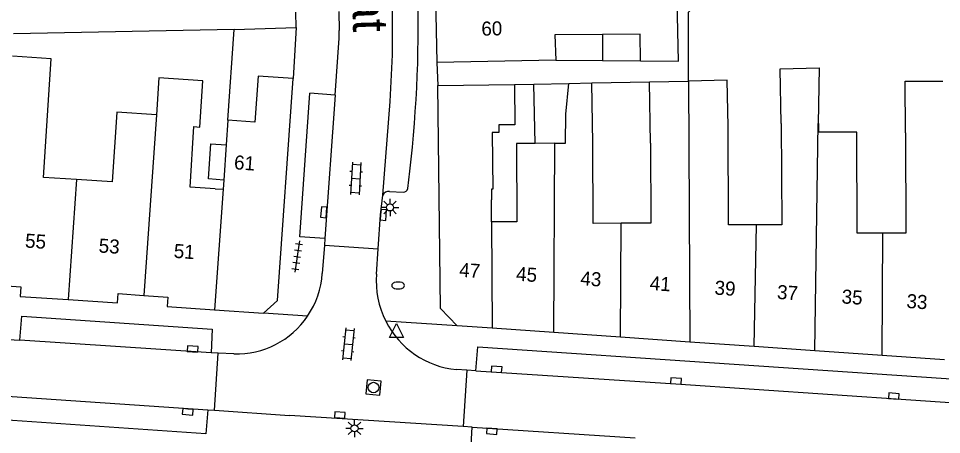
# Model space of a CAD drawing. Extents: x 132998 to 136004, y 396998 to 398512.
# Drawn here: x 133158 to 133223.8, y 397332.1 to 397361.7 of the extents above; entities that cross this region are included whole.
import ezdxf

# ---------------------------------------------------------------- set-up
doc = ezdxf.new("R2010")
doc.units = 0
for name, color, linetype in [('gg-afsc-erfafscheiding', 7, 'Continuous'), ('gg-afsc-muur', 7, 'Continuous'), ('gg-anno-huisnummerreeks BGT', 7, 'Continuous'), ('gg-anno-openbare ruimte label', 7, 'Continuous'), ('gg-bbg-gedigitaliseerde bebouwing', 7, 'Continuous'), ('gg-bbg-gedigitaliseerde bijgebouw', 7, 'Continuous'), ('gg-bbg-hoofdgebouw', 7, 'Continuous'), ('gg-bbg-luifel en loopbrug', 7, 'Continuous'), ('gg-bbg-tussenscheiding', 7, 'Continuous'), ('gg-knt-verharding', 7, 'Continuous'), ('gg-knt-verharding nz', 7, 'Continuous'), ('gt-grn-weggrens', 7, 'Continuous'), ('gt-symb-brandkraan', 7, 'Continuous'), ('gt-symb-klinker verharding', 7, 'Continuous'), ('gt-symb-kolk', 7, 'Continuous'), ('gt-symb-lichtmast', 7, 'Continuous'), ('gt-symb-rioolschacht', 7, 'Continuous'), ('gt-symb-tegel verharding', 7, 'Continuous'), ('gt-symb-waterafsluiter', 7, 'Continuous')]:
    doc.layers.add(name, color=color, linetype=linetype)

# ---------------------------------------------------------------- blocks, each defined once
blk = doc.blocks.new('gt0-KOLK')
at = {"layer": 'gt-symb-kolk'}
blk.add_lwpolyline([(0, 0), (0.375, 0), (0.375, 0.4), (-0.375, 0.4), (-0.375, 0), (0, 0)], dxfattribs=at)
blk = doc.blocks.new('gt0-KL1')
at = {"layer": 'gt-symb-klinker verharding'}
for p, q in [((-1.15, 0.3), (1.15, 0.3)), ((-1, -0.3), (-1, 0.3)), ((-0.5, 0.3), (-0.5, 0.45)), ((0, -0.3), (0, 0.3)), ((0.5, 0.3), (0.5, 0.45)), ((1, -0.3), (1, 0.3)), ((-1.15, -0.3), (1.15, -0.3)), ((-0.5, -0.45), (-0.5, -0.3)), ((0.5, -0.45), (0.5, -0.3))]:
    blk.add_line(p, q, dxfattribs=at)
blk = doc.blocks.new('gt0-LMAST')
at = {"layer": 'gt-symb-lichtmast'}
for p, q in [((-0.182, 0.173), (-0.447, 0.438)), ((-0.005, 0.246), (-0.005, 0.621)), ((0.172, 0.173), (0.437, 0.438)), ((-0.255, -0.004), (-0.63, -0.004)), ((-0.182, -0.181), (-0.447, -0.446)), ((-0.005, -0.254), (-0.005, -0.629)), ((0.437, -0.446), (0.172, -0.181)), ((0.245, -0.004), (0.62, -0.004))]:
    blk.add_line(p, q, dxfattribs=at)
blk.add_circle((-0.005, -0.004), 0.25, dxfattribs=at)
blk = doc.blocks.new('gt0-WAFSL')
at = {"layer": 'gt-symb-waterafsluiter'}
for p, q in [((-0.5, -0.333), (0, 0.667)), ((0, 0.667), (0.5, -0.333)), ((0.5, -0.333), (-0.5, -0.333))]:
    blk.add_line(p, q, dxfattribs=at)
blk = doc.blocks.new('gt0-BR')
at = {"layer": 'gt-symb-brandkraan'}
for centre, radius, start, end in [((-0.244, 0), 0.206, 107.56694, 252.43307), ((0.599, -2.664), 3, 106.89205, 107.56694), ((0, -0.691), 0.938, 73.10799, 106.89205), ((-0.599, -2.664), 3, 72.43309, 73.10799), ((0.244, 0), 0.206, 287.56695, 72.43309), ((0.599, 2.664), 3, 252.43307, 253.10797), ((0, 0.691), 0.938, 253.10797, 286.89206), ((-0.599, 2.664), 3, 286.89206, 287.56695)]:
    blk.add_arc(centre, radius, start, end, dxfattribs=at)
blk = doc.blocks.new('gt0-TEG1')
at = {"layer": 'gt-symb-tegel verharding'}
for p, q in [((-1.125, 0), (1.125, 0)), ((-0.9, -0.25), (-0.9, 0.25)), ((-0.45, -0.25), (-0.45, 0.25)), ((0, -0.25), (0, 0.25)), ((0.45, -0.25), (0.45, 0.25)), ((0.9, -0.25), (0.9, 0.25))]:
    blk.add_line(p, q, dxfattribs=at)
blk = doc.blocks.new('gt0-RS')
at = {"layer": 'gt-symb-rioolschacht'}
blk.add_lwpolyline([(-0.5, -0.5), (0.5, -0.5), (0.5, 0.5), (-0.5, 0.5)], close=True, dxfattribs=at)
blk.add_circle((0, 0), 0.375, dxfattribs=at)

msp = doc.modelspace()

# ---------------------------------------------------------------- linework, layer by layer
at = {"layer": 'gg-afsc-erfafscheiding'}
for p, q in [((133173.382, 397360.928), (133157.638, 397360.616)), ((133172.931, 397354.473), (133173.382, 397360.928)), ((133196.312, 397358.74), (133199.636, 397358.71)), ((133193.365, 397357.015), (133194.748, 397357.042)), ((133198.874, 397357.122), (133202.985, 397357.202))]:
    msp.add_line(p, q, dxfattribs=at)
msp.add_lwpolyline([(133210.26, 397366.607), (133206.585, 397366.607), (133206.656, 397362.968), (133205.758, 397362.13), (133205.758, 397357.256)], dxfattribs=at)
at = {"layer": 'gg-afsc-muur'}
for p, q in [((133173.382, 397360.928), (133177.791, 397361.06)), ((133177.791, 397361.06), (133177.59, 397357.43))]:
    msp.add_line(p, q, dxfattribs=at)
at = {"layer": 'gg-bbg-gedigitaliseerde bebouwing'}
for p, q in [((133196.312, 397358.74), (133187.83, 397358.57)), ((133187.89, 397356.95), (133193.365, 397357.015)), ((133197.24, 397357.09), (133198.874, 397357.122)), ((133198.957, 397352.835), (133198.874, 397357.122)), ((133202.985, 397357.202), (133205.758, 397357.256)), ((133203.07, 397352.825), (133202.985, 397357.202)), ((133205.758, 397357.256), (133205.785, 397357.256)), ((133172.931, 397354.473), (133172.808, 397352.705)), ((133172.808, 397352.705), (133172.633, 397350.205)), ((133172.633, 397350.205), (133172.587, 397349.546)), ((133172.022, 397349.583), (133172.587, 397349.546)), ((133191.735, 397347.227), (133191.728, 397348.786))]:
    msp.add_line(p, q, dxfattribs=at)
for points in [[(133202.345, 397358.686), (133205.062, 397358.661), (133204.978, 397362.961)], [(133199.652, 397360.565), (133196.253, 397360.538), (133196.312, 397358.74)], [(133202.345, 397358.686), (133202.33, 397360.587), (133199.652, 397360.565)], [(133160.121, 397355.532), (133160.338, 397358.849), (133157.583, 397359.029)], [(133212.385, 397354.223), (133212.309, 397358.134), (133215.093, 397358.188), (133215.032, 397354.236)], [(133170.514, 397354.01), (133170.94, 397353.982), (133171.155, 397357.273), (133168.02, 397357.478), (133167.837, 397354.859)], [(133177.59, 397357.43), (133175.088, 397357.605), (133174.86, 397354.338), (133172.931, 397354.473)], [(133193.365, 397357.015), (133193.399, 397354.147), (133192.241, 397354.133), (133192.247, 397353.586), (133191.774, 397353.581), (133191.822, 397349.558), (133191.718, 397349.556), (133191.728, 397348.786)], [(133208.594, 397354.028), (133208.53, 397357.309), (133205.785, 397357.256)], [(133221.241, 397353.575), (133221.226, 397357.246), (133223.902, 397357.259)], [(133162.134, 397350.232), (133159.784, 397350.386), (133160.121, 397355.532)], [(133167.837, 397354.859), (133165.007, 397355.045), (133164.68, 397350.065), (133162.134, 397350.232)], [(133212.385, 397354.223), (133212.42, 397347.023), (133210.617, 397347.014)], [(133219.639, 397346.416), (133217.803, 397346.407), (133217.768, 397353.624), (133215.079, 397353.611), (133215.076, 397354.236), (133215.032, 397354.236)], [(133172.022, 397349.583), (133170.231, 397349.701), (133170.514, 397354.01)], [(133210.617, 397347.014), (133208.627, 397347.005), (133208.594, 397354.028)], [(133221.241, 397353.575), (133221.275, 397346.424), (133219.639, 397346.416)], [(133194.83, 397352.817), (133193.506, 397352.811), (133193.531, 397347.235), (133191.735, 397347.227)], [(133200.974, 397347.12), (133198.982, 397347.111), (133198.957, 397352.835)], [(133203.07, 397352.825), (133203.095, 397347.129), (133200.974, 397347.12)]]:
    msp.add_lwpolyline(points, dxfattribs=at)
at = {"layer": 'gg-bbg-gedigitaliseerde bijgebouw'}
for p, q in [((133194.748, 397357.042), (133197.24, 397357.09)), ((133194.83, 397352.817), (133194.748, 397357.042))]:
    msp.add_line(p, q, dxfattribs=at)
at = {"layer": 'gg-bbg-hoofdgebouw'}
for p, q in [((133187.741, 397363.173), (133187.83, 397358.57)), ((133156.439, 397342.708), (133158.177, 397342.588)), ((133165.11, 397342.113), (133166.935, 397341.988)), ((133171.987, 397340.953), (133175.47, 397340.71)), ((133191.768, 397339.646), (133189.27, 397339.82)), ((133196.182, 397339.338), (133191.768, 397339.646)), ((133200.926, 397339.008), (133196.182, 397339.338)), ((133205.864, 397338.663), (133200.926, 397339.008)), ((133210.45, 397338.344), (133205.864, 397338.663)), ((133214.782, 397338.042), (133210.45, 397338.344)), ((133219.578, 397337.708), (133214.782, 397338.042)), ((133224.031, 397337.397), (133219.578, 397337.708))]:
    msp.add_line(p, q, dxfattribs=at)
for points in [[(133175.47, 397340.71), (133176.47, 397341.61), (133177.59, 397357.43)], [(133189.27, 397339.82), (133188.09, 397341.04), (133187.89, 397356.95)], [(133158.177, 397342.588), (133158.132, 397341.912), (133161.535, 397341.683)], [(133161.535, 397341.683), (133165.065, 397341.446), (133165.11, 397342.113)], [(133166.935, 397341.988), (133168.65, 397341.87), (133168.6, 397341.19), (133171.987, 397340.953)]]:
    msp.add_lwpolyline(points, dxfattribs=at)
at = {"layer": 'gg-bbg-luifel en loopbrug'}
for p, q in [((133199.652, 397360.565), (133199.636, 397358.71)), ((133199.636, 397358.71), (133202.345, 397358.686))]:
    msp.add_line(p, q, dxfattribs=at)
msp.add_lwpolyline([(133172.633, 397350.205), (133171.545, 397350.28), (133171.718, 397352.776), (133172.808, 397352.705)], dxfattribs=at)
at = {"layer": 'gg-bbg-tussenscheiding'}
for p, q in [((133205.785, 397357.256), (133205.864, 397338.663)), ((133167.837, 397354.859), (133166.935, 397341.988)), ((133214.782, 397338.042), (133215.032, 397354.236)), ((133196.234, 397352.823), (133194.83, 397352.817)), ((133196.182, 397339.338), (133196.234, 397352.823)), ((133162.134, 397350.232), (133161.535, 397341.683)), ((133172.587, 397349.546), (133171.987, 397340.953)), ((133191.735, 397347.227), (133191.768, 397339.646)), ((133200.926, 397339.008), (133200.974, 397347.12)), ((133210.45, 397338.344), (133210.617, 397347.014)), ((133219.578, 397337.708), (133219.639, 397346.416))]:
    msp.add_line(p, q, dxfattribs=at)
msp.add_lwpolyline([(133196.234, 397352.823), (133197.001, 397352.826), (133197.036, 397354.885), (133197.24, 397357.09)], dxfattribs=at)
at = {"layer": 'gg-knt-verharding'}
for p, q in [((133180.831, 397362.218), (133180.859, 397360.853)), ((133178.067, 397346.15), (133178.779, 397356.387)), ((133180.588, 397356.261), (133178.779, 397356.387)), ((133185.763, 397349.59), (133185.902, 397350.842)), ((133184.448, 397349.391), (133185.431, 397349.341)), ((133179.845, 397346.031), (133178.067, 397346.15)), ((133179.809, 397345.558), (133179.659, 397343.554)), ((133179.845, 397346.031), (133179.809, 397345.558)), ((133179.809, 397345.558), (133183.657, 397345.309)), ((133183.532, 397343.495), (133183.657, 397345.309)), ((133156.263, 397338.904), (133158.102, 397338.807)), ((133172.242, 397337.87), (133171.742, 397337.896)), ((133171.989, 397333.808), (133172.242, 397337.87)), ((133173.357, 397337.811), (133172.242, 397337.87)), ((133189.96, 397336.657), (133189.233, 397336.703)), ((133189.96, 397336.657), (133189.697, 397332.649)), ((133190.605, 397336.616), (133189.96, 397336.657)), ((133171.492, 397333.843), (133171.989, 397333.808)), ((133171.989, 397333.808), (133177.327, 397333.431)), ((133189.697, 397332.649), (133177.327, 397333.431)), ((133190.354, 397332.608), (133189.697, 397332.649)), ((133190.246, 397330.915), (133190.354, 397332.608))]:
    msp.add_line(p, q, dxfattribs=at)
for points in [[(133180.588, 397356.261), (133180.87, 397360.3), (133180.859, 397360.853)], [(133183.657, 397345.309), (133183.824, 397347.733), (133183.978, 397349.137)], [(133158.102, 397338.807), (133158.243, 397340.496), (133171.82, 397339.572), (133171.742, 397337.896)], [(133190.605, 397336.616), (133190.744, 397338.317), (133227.3, 397335.852), (133227.218, 397334.154)], [(133171.492, 397333.843), (133171.371, 397332.124), (133136.864, 397334.5), (133136.936, 397336.172)]]:
    msp.add_lwpolyline(points, dxfattribs=at)
for centre, radius, start, end in [((133097.313, 397361.2), 89.193, 353.33087, 2.11105), ((133185.452, 397349.659), 0.319, 266.2488, 347.491), ((133184.383, 397348.949), 0.447, 81.66312, 155.11272), ((133173.526, 397343.951), 6.146, 325.91357, 356.29387), ((133189.826, 397342.996), 6.314, 175.46528, 206.81201), ((133173.53, 397343.952), 6.143, 268.38955, 325.89389), ((133189.834, 397342.994), 6.32, 206.76844, 264.54505)]:
    msp.add_arc(centre, radius, start, end, dxfattribs=at)
at = {"layer": 'gg-knt-verharding nz'}
for p, q in [((133184.67, 397361.66), (133184.435, 397375.917)), ((133180.588, 397356.261), (133179.845, 397346.031)), ((133171.742, 397337.896), (133158.102, 397338.807)), ((133136.936, 397336.172), (133171.492, 397333.843)), ((133190.354, 397332.608), (133201.972, 397331.84))]:
    msp.add_line(p, q, dxfattribs=at)
for points in [[(133183.978, 397349.137), (133184.5, 397355.79), (133184.67, 397359.13), (133184.67, 397361.66)], [(133190.605, 397336.616), (133204.874, 397335.695), (133227.218, 397334.154)]]:
    msp.add_lwpolyline(points, dxfattribs=at)
at = {"layer": 'gt-grn-weggrens'}
for p, q in [((133177.791, 397361.06), (133177.77, 397362.16)), ((133187.83, 397358.57), (133187.89, 397356.95)), ((133178.616, 397340.507), (133175.47, 397340.71)), ((133189.27, 397339.82), (133184.191, 397340.148))]:
    msp.add_line(p, q, dxfattribs=at)

# ---------------------------------------------------------------- block references
at = {"layer": 'gt-symb-brandkraan'}
msp.add_blockref('gt0-BR', (133185.07, 397342.692), dxfattribs=at)
at = {"layer": 'gt-symb-klinker verharding'}
for p, rotation in [((133182.049, 397350.316), -93.26885295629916), ((133181.522, 397338.509), -95.51097695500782)]:
    msp.add_blockref('gt0-KL1', p, dxfattribs=dict(at, rotation=rotation))
at = {"layer": 'gt-symb-kolk'}
for p, rotation in [((133179.965, 397347.893), 85.06501407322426), ((133183.824, 397347.733), -94.35915162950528), ((133170.41, 397337.975), -3.3832876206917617), ((133192.079, 397336.516), -3.897896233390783), ((133204.874, 397335.695), -3.669254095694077), ((133220.402, 397334.608), -4.012171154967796), ((133170.082, 397333.89), 175.9266355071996), ((133180.904, 397333.266), -3.9550376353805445), ((133191.763, 397332.508), 175.926635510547)]:
    msp.add_blockref('gt0-KOLK', p, dxfattribs=dict(at, rotation=rotation))
at = {"layer": 'gt-symb-lichtmast', "rotation": 180}
msp.add_blockref('gt0-LMAST', (133184.487, 397348.246), dxfattribs=at)
at = {"layer": 'gt-symb-lichtmast'}
msp.add_blockref('gt0-LMAST', (133181.965, 397332.518), dxfattribs=at)
at = {"layer": 'gt-symb-rioolschacht', "rotation": -5.334440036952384}
msp.add_blockref('gt0-RS', (133183.315, 397335.418), dxfattribs=at)
at = {"layer": 'gt-symb-tegel verharding', "rotation": -98.56758990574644}
msp.add_blockref('gt0-TEG1', (133177.872, 397344.753), dxfattribs=at)
at = {"layer": 'gt-symb-waterafsluiter'}
msp.add_blockref('gt0-WAFSL', (133184.948, 397339.307), dxfattribs=at)

# ---------------------------------------------------------------- texts
at = {"layer": 'gg-anno-huisnummerreeks BGT'}
for s, rotation, p in [('60', 1.1, (133191.016, 397360.488)), ('61', 356, (133173.347, 397350.977)), ('55', 356.2, (133158.448, 397345.397)), ('53', 356.2, (133163.696, 397345.045)), ('51', 356, (133169.049, 397344.667)), ('47', 356, (133189.403, 397343.319)), ('45', 356, (133193.461, 397343.036)), ('43', 356, (133198.042, 397342.717)), ('41', 356, (133202.99, 397342.372)), ('39', 356, (133207.608, 397342.05)), ('37', 356, (133212.063, 397341.74)), ('35', 356, (133216.668, 397341.419)), ('33', 356, (133221.292, 397341.096))]:
    msp.add_text(s, height=1, rotation=rotation, dxfattribs=at).set_placement(p)
at = {"layer": 'gg-anno-openbare ruimte label'}
msp.add_text('Lieven de Keijstraat', height=2.5, rotation=271.6, dxfattribs=at).set_placement((133181.045, 397390.065))

doc.saveas('drawing.dxf')
